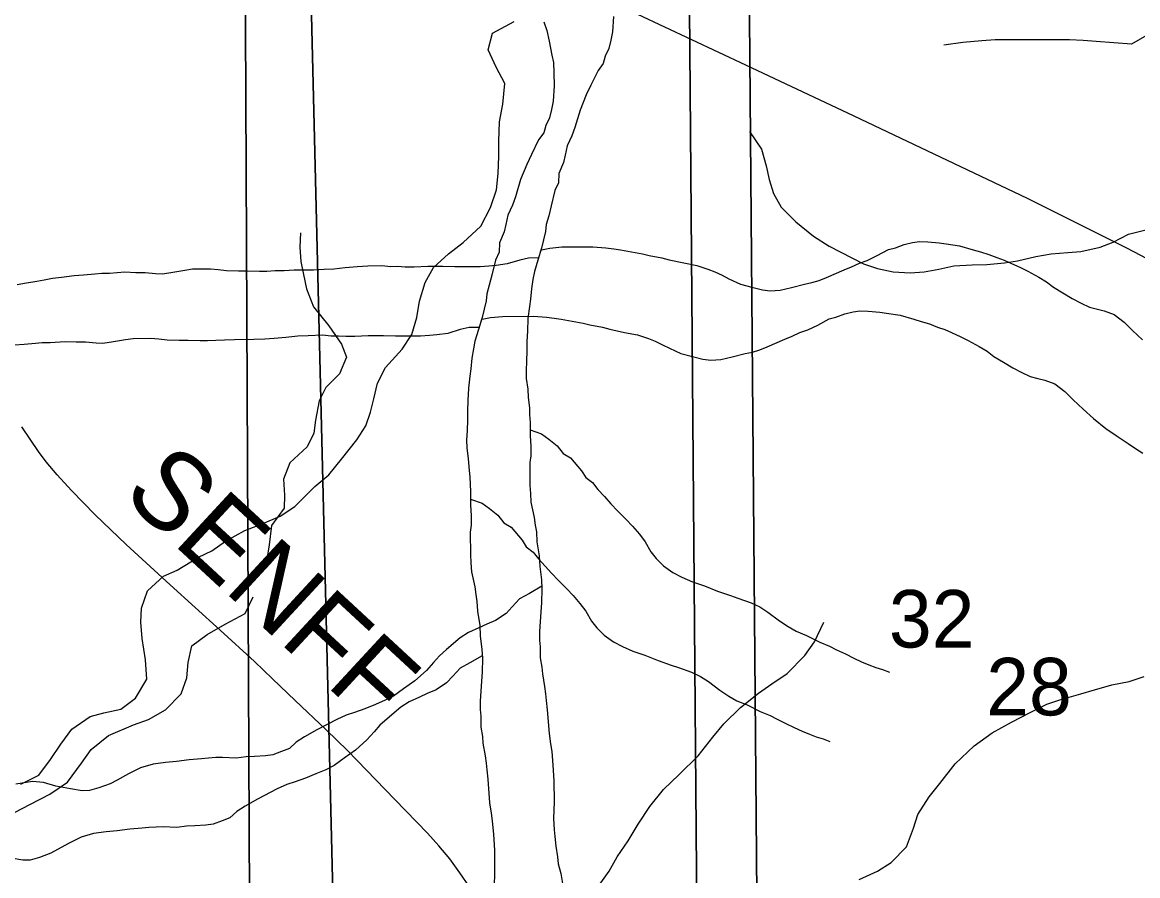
# Model space of a CAD drawing. Extents: x -21.1 to 50.3, y -4.9 to 22.1.
# Drawn here: x 6.307 to 7.119, y 17.303 to 17.924 of the extents above; entities that cross this region are included whole.
import ezdxf

# ---------------------------------------------------------------- set-up
doc = ezdxf.new("R2010")
doc.units = 0
for name, color, linetype in [('GM_X_Minor_River', 7, 'Continuous'), ('GM_X_Section', 7, 'Continuous'), ('GM_X_Section_Text', 7, 'Continuous'), ('GM_X_Township_Road', 7, 'Continuous'), ('GM_X_Township_Road_Text', 7, 'Continuous'), ('GM_X_US_Route', 7, 'Continuous')]:
    doc.layers.add(name, color=color, linetype=linetype)

msp = doc.modelspace()

# ---------------------------------------------------------------- linework, layer by layer
at = {"layer": 'GM_X_Minor_River'}
for points in [[(6.46887, 17.55403), (6.48147, 17.55877), (6.49447, 17.56428), (6.50522, 17.57133), (6.51988, 17.58592), (6.52989, 17.59451), (6.53918, 17.60576), (6.55041, 17.62003), (6.55703, 17.63018), (6.56022, 17.64001), (6.56265, 17.64985), (6.56549, 17.66121), (6.57136, 17.67251), (6.58334, 17.68601), (6.59034, 17.69654), (6.59395, 17.70902), (6.59604, 17.72076), (6.60005, 17.73438), (6.60629, 17.7453), (6.61708, 17.7554), (6.62784, 17.76359), (6.64057, 17.77555), (6.64761, 17.78912), (6.65199, 17.80197), (6.65331, 17.81373), (6.65388, 17.82626), (6.65368, 17.83728), (6.65427, 17.85132), (6.65675, 17.8642), (6.65813, 17.87938), (6.65186, 17.89125), (6.64597, 17.90387), (6.6492, 17.91598), (6.6649, 17.92448)], [(6.6865, 17.92424), (6.68882, 17.9178), (6.69038, 17.91021), (6.69235, 17.89996), (6.69352, 17.89465), (6.69394, 17.88706), (6.69399, 17.87756), (6.6933, 17.86654), (6.69219, 17.86045), (6.6907, 17.85437), (6.68806, 17.84865), (6.68657, 17.84333), (6.68279, 17.83837), (6.67752, 17.8277), (6.67414, 17.82047), (6.66963, 17.80943), (6.6659, 17.79687), (6.66365, 17.79078), (6.66026, 17.78354), (6.65878, 17.7767), (6.65767, 17.77137), (6.65428, 17.76338), (6.65394, 17.75654), (6.65131, 17.75082), (6.64871, 17.73979), (6.64685, 17.73257), (6.64498, 17.7261), (6.64463, 17.72116), (6.64165, 17.70899), (6.63903, 17.70023), (6.63641, 17.69186), (6.6353, 17.68616), (6.6342, 17.67931), (6.63348, 17.67171), (6.63275, 17.66639), (6.63166, 17.65765), (6.63133, 17.64853), (6.63099, 17.64093), (6.63102, 17.63447), (6.63069, 17.62649), (6.63035, 17.62003), (6.63038, 17.61395), (6.63156, 17.60636), (6.63198, 17.60029), (6.63278, 17.59269), (6.63281, 17.58775), (6.63322, 17.58206), (6.63327, 17.57256), (6.6337, 17.56459), (6.63374, 17.55775), (6.633, 17.55281), (6.6331, 17.53609), (6.63351, 17.5304), (6.63393, 17.52394), (6.63627, 17.51294), (6.63707, 17.50724), (6.63786, 17.50231), (6.63828, 17.49509), (6.63986, 17.48485), (6.64028, 17.47725), (6.64148, 17.46738), (6.64189, 17.46093), (6.64157, 17.45067), (6.64123, 17.44421), (6.64016, 17.42977), (6.6402, 17.42369), (6.64061, 17.41875), (6.64065, 17.41077)], [(6.73728, 17.92807), (6.73658, 17.91705), (6.73547, 17.91097), (6.73399, 17.90488), (6.73135, 17.89917), (6.72986, 17.89384), (6.72608, 17.88889), (6.72081, 17.87822), (6.71743, 17.87098), (6.71292, 17.85994), (6.70919, 17.84739), (6.70694, 17.8413), (6.70355, 17.83406), (6.70207, 17.82721), (6.70096, 17.82189), (6.69757, 17.81389), (6.69723, 17.80705), (6.6946, 17.80134), (6.692, 17.79031), (6.69013, 17.78308), (6.68827, 17.77661), (6.68791, 17.77167), (6.68493, 17.7595), (6.68232, 17.75075), (6.6797, 17.74238), (6.67859, 17.73667), (6.67749, 17.72983), (6.67677, 17.72223), (6.67604, 17.71691), (6.67495, 17.70816), (6.67461, 17.69904), (6.67428, 17.69145), (6.67431, 17.68499), (6.67398, 17.67701), (6.67363, 17.67055), (6.67367, 17.66447), (6.67485, 17.65688), (6.67527, 17.6508), (6.67607, 17.64321), (6.6761, 17.63827), (6.67651, 17.63257), (6.67656, 17.62308), (6.67699, 17.6151), (6.67703, 17.60827), (6.67629, 17.60332), (6.67639, 17.58661), (6.6768, 17.58091), (6.67722, 17.57446), (6.67956, 17.56345), (6.68036, 17.55776), (6.68115, 17.55283), (6.68157, 17.54561), (6.68315, 17.53536), (6.68357, 17.52777), (6.68476, 17.5179), (6.68518, 17.51144), (6.68486, 17.50118), (6.68451, 17.49472), (6.68345, 17.48028), (6.68349, 17.4742), (6.6839, 17.46927), (6.68394, 17.46129)], [(7.1272, 17.91528), (7.11469, 17.90807), (7.1018, 17.90883), (7.08891, 17.90996), (7.07944, 17.91072), (7.06958, 17.9111), (7.01538, 17.91109), (7.00552, 17.91033), (6.99187, 17.90919), (6.97785, 17.90729)], [(6.83642, 17.84432), (6.84514, 17.83143), (6.84854, 17.81929), (6.85081, 17.80943), (6.85384, 17.79919), (6.85952, 17.78933), (6.87013, 17.77871), (6.88301, 17.76809), (6.89438, 17.76089), (6.91939, 17.748), (6.92962, 17.74458), (6.94099, 17.74231), (6.9535, 17.74155), (6.96373, 17.74231), (6.97435, 17.74421), (6.98534, 17.74649), (6.99861, 17.74725), (7.00922, 17.74763), (7.02211, 17.74877), (7.03159, 17.75028), (7.04486, 17.75332), (7.05623, 17.75522), (7.06836, 17.75636), (7.07784, 17.75712), (7.09186, 17.76015), (7.10134, 17.76394), (7.11234, 17.76964), (7.12599, 17.77305)], [(6.50926, 17.7707), (6.50887, 17.76008), (6.50963, 17.74985), (6.51151, 17.74036), (6.51378, 17.72974), (6.51871, 17.71685), (6.53007, 17.70282), (6.53916, 17.68954), (6.54294, 17.68006), (6.53763, 17.66793), (6.52777, 17.65806), (6.52284, 17.6482), (6.52018, 17.63417), (6.51904, 17.62469), (6.5141, 17.61483), (6.50159, 17.60307), (6.49703, 17.59131), (6.49778, 17.57955), (6.4974, 17.57007), (6.48829, 17.55755), (6.48639, 17.54352), (6.48487, 17.5329)], [(6.68419, 17.75702), (6.68494, 17.75836), (6.69103, 17.75953), (6.69978, 17.76034), (6.72223, 17.76046), (6.73175, 17.75976), (6.73747, 17.75903), (6.74242, 17.7583), (6.75842, 17.75534), (6.76338, 17.75423), (6.77252, 17.75238), (6.77786, 17.75089), (6.78853, 17.74867), (6.79806, 17.74682), (6.80607, 17.74421), (6.81103, 17.74234), (6.81637, 17.73971), (6.82133, 17.73707), (6.82973, 17.73332), (6.83811, 17.73109), (6.84574, 17.72923), (6.85145, 17.7285), (6.85868, 17.72892), (6.86704, 17.73087), (6.87654, 17.7332), (6.88187, 17.73437), (6.88719, 17.73592), (6.89251, 17.73822), (6.90542, 17.74361), (6.91073, 17.74592), (6.91643, 17.74861), (6.92213, 17.75054), (6.92934, 17.754), (6.93769, 17.7586), (6.94263, 17.75977), (6.94909, 17.76209), (6.95517, 17.76364), (6.96011, 17.76443), (6.96621, 17.76408), (6.97458, 17.76337), (6.97954, 17.76263), (6.98944, 17.76117), (6.99935, 17.75818), (7.00469, 17.75669), (7.01079, 17.75483), (7.01651, 17.75258), (7.02185, 17.75071), (7.02682, 17.74846), (7.03368, 17.74545), (7.03903, 17.74282), (7.04705, 17.73831), (7.05277, 17.73492), (7.05774, 17.73115), (7.06462, 17.72701), (7.07149, 17.72287), (7.07798, 17.71948), (7.08409, 17.71648), (7.08981, 17.71499), (7.09476, 17.71388), (7.10201, 17.71126), (7.10927, 17.7056), (7.1154, 17.69956), (7.12267, 17.69276)], [(6.68279, 17.75231), (6.67546, 17.75223), (6.669, 17.75068), (6.65988, 17.74797), (6.65189, 17.74678), (6.64657, 17.74637), (6.6401, 17.74596), (6.62183, 17.74586), (6.61307, 17.74619), (6.60203, 17.74613), (6.59214, 17.7457), (6.58567, 17.74566), (6.58033, 17.74601), (6.57501, 17.74598), (6.56853, 17.74671), (6.55826, 17.74627), (6.55065, 17.74585), (6.5419, 17.74504), (6.53353, 17.74423), (6.52668, 17.74382), (6.51868, 17.74339), (6.5046, 17.74332), (6.49737, 17.7429), (6.4909, 17.74286), (6.48481, 17.74245), (6.47948, 17.74242), (6.47073, 17.74275), (6.46426, 17.74272), (6.4555, 17.74305), (6.44941, 17.74377), (6.4437, 17.74412), (6.43075, 17.74405), (6.42505, 17.74326), (6.4163, 17.74169), (6.4087, 17.74051), (6.40375, 17.74087), (6.39613, 17.74158), (6.38928, 17.74155), (6.38128, 17.74188), (6.37025, 17.74106), (6.36454, 17.74103), (6.35959, 17.74062), (6.35122, 17.73982), (6.34437, 17.7394), (6.33525, 17.73821), (6.32878, 17.73741), (6.32269, 17.73624), (6.31737, 17.73507), (6.30977, 17.73389), (6.30292, 17.73272)], [(6.6409, 17.7065), (6.64165, 17.70784), (6.64774, 17.70902), (6.65649, 17.70983), (6.67894, 17.70995), (6.68846, 17.70924), (6.69418, 17.70851), (6.69913, 17.70778), (6.71513, 17.70483), (6.72009, 17.70372), (6.72923, 17.70187), (6.73457, 17.70038), (6.74524, 17.69815), (6.75477, 17.69631), (6.76278, 17.69369), (6.76774, 17.69182), (6.77308, 17.68919), (6.77804, 17.68656), (6.78644, 17.68281), (6.79482, 17.68057), (6.80245, 17.67872), (6.80816, 17.67799), (6.81539, 17.6784), (6.82375, 17.68035), (6.83326, 17.68268), (6.83858, 17.68385), (6.8439, 17.6854), (6.84922, 17.68771), (6.86213, 17.6931), (6.86745, 17.6954), (6.87314, 17.6981), (6.87884, 17.70003), (6.88605, 17.70348), (6.8944, 17.70809), (6.89934, 17.70925), (6.9058, 17.71157), (6.91188, 17.71312), (6.91682, 17.71391), (6.92292, 17.71356), (6.9313, 17.71285), (6.93625, 17.71212), (6.94615, 17.71065), (6.95606, 17.70767), (6.9614, 17.70618), (6.9675, 17.70431), (6.97323, 17.70206), (6.97856, 17.70019), (6.98353, 17.69794), (6.99039, 17.69494), (6.99574, 17.69231), (7.00376, 17.68779), (7.00949, 17.68441), (7.01445, 17.68064), (7.02133, 17.67649), (7.0282, 17.67235), (7.03469, 17.66897), (7.0408, 17.66596), (7.04652, 17.66448), (7.05147, 17.66336), (7.05872, 17.66074), (7.06598, 17.65509), (7.07211, 17.64904), (7.07938, 17.64224), (7.08703, 17.63545), (7.09582, 17.62828), (7.10347, 17.623), (7.11225, 17.61735), (7.1176, 17.61358), (7.12295, 17.61019)], [(6.6395, 17.70179), (6.63217, 17.70172), (6.62571, 17.70016), (6.61659, 17.69745), (6.6086, 17.69627), (6.60328, 17.69586), (6.59681, 17.69544), (6.57854, 17.69534), (6.56978, 17.69568), (6.55874, 17.69561), (6.54885, 17.69518), (6.54238, 17.69515), (6.53705, 17.6955), (6.53172, 17.69547), (6.52524, 17.69619), (6.51497, 17.69575), (6.50736, 17.69533), (6.49861, 17.69453), (6.49024, 17.69372), (6.48339, 17.6933), (6.4754, 17.69288), (6.46131, 17.6928), (6.45408, 17.69238), (6.44761, 17.69235), (6.44152, 17.69193), (6.4362, 17.6919), (6.42744, 17.69224), (6.42097, 17.6922), (6.41221, 17.69253), (6.40612, 17.69326), (6.40041, 17.69361), (6.38746, 17.69354), (6.38176, 17.69275), (6.37301, 17.69118), (6.36541, 17.69), (6.36046, 17.69035), (6.35284, 17.69107), (6.34599, 17.69103), (6.33799, 17.69137), (6.32696, 17.69055), (6.32125, 17.69051), (6.31631, 17.69011), (6.30793, 17.6893), (6.30108, 17.68889)], [(6.67654, 17.62726), (6.68493, 17.62426), (6.69028, 17.62049), (6.6964, 17.61559), (6.70062, 17.60991), (6.70596, 17.6069), (6.71401, 17.59745), (6.71708, 17.59253), (6.72205, 17.58876), (6.72589, 17.58384), (6.73086, 17.57855), (6.73546, 17.57326), (6.74044, 17.56796), (6.74656, 17.56192), (6.75116, 17.55701), (6.75614, 17.55134), (6.76036, 17.54566), (6.76459, 17.53847), (6.76842, 17.53355), (6.77378, 17.52826), (6.78066, 17.52336), (6.78715, 17.51998), (6.79478, 17.5166), (6.80355, 17.51361), (6.81309, 17.50986), (6.82262, 17.50649), (6.82796, 17.50462), (6.8375, 17.50126), (6.84398, 17.49825), (6.84971, 17.49448), (6.85812, 17.48807), (6.86462, 17.48393), (6.87035, 17.48054), (6.87798, 17.47754), (6.88752, 17.47266), (6.89477, 17.46966), (6.89973, 17.46703), (6.90622, 17.46402), (6.91233, 17.46102), (6.91805, 17.45839), (6.92339, 17.45614), (6.92835, 17.45427), (6.93331, 17.45277), (6.93827, 17.4509)], [(6.63325, 17.57674), (6.64164, 17.57375), (6.64699, 17.56998), (6.65311, 17.56507), (6.65733, 17.5594), (6.66267, 17.55639), (6.67072, 17.54693), (6.6738, 17.54201), (6.67876, 17.53824), (6.6826, 17.53332), (6.68758, 17.52803), (6.69217, 17.52274), (6.69715, 17.51745), (6.70327, 17.5114), (6.70787, 17.50649), (6.71285, 17.50082), (6.71707, 17.49515), (6.7213, 17.48795), (6.72513, 17.48303), (6.73049, 17.47774), (6.73737, 17.47284), (6.74386, 17.46946), (6.75149, 17.46608), (6.76026, 17.46309), (6.7698, 17.45934), (6.77933, 17.45598), (6.78467, 17.45411), (6.79421, 17.45074), (6.80069, 17.44774), (6.80642, 17.44397), (6.81484, 17.43756), (6.82133, 17.43341), (6.82706, 17.43003), (6.83469, 17.42703), (6.84423, 17.42214), (6.85148, 17.41914), (6.85644, 17.41651), (6.86293, 17.41351), (6.86904, 17.4105), (6.87476, 17.40787), (6.8801, 17.40562), (6.88506, 17.40375), (6.89002, 17.40226), (6.89498, 17.40039)], [(6.30571, 17.36922), (6.31873, 17.37586), (6.32726, 17.38713), (6.33465, 17.39841), (6.3428, 17.40931), (6.35624, 17.4186), (6.36615, 17.42111), (6.37835, 17.42396), (6.38911, 17.43178), (6.3973, 17.44571), (6.39638, 17.45978), (6.39396, 17.47539), (6.393, 17.48718), (6.39354, 17.49743), (6.39791, 17.5099), (6.40948, 17.52074), (6.41942, 17.52515), (6.43514, 17.5344), (6.44471, 17.5392), (6.45469, 17.54626), (6.46887, 17.55403)], [(6.68506, 17.51329), (6.67607, 17.50797), (6.66886, 17.50413), (6.66356, 17.49841), (6.65902, 17.49344), (6.65143, 17.48846), (6.64498, 17.48577), (6.63928, 17.48308), (6.63169, 17.47962), (6.62562, 17.47579), (6.61577, 17.46737), (6.61047, 17.46279), (6.60631, 17.45783), (6.60101, 17.4521), (6.59268, 17.44446), (6.58434, 17.43871), (6.57714, 17.43335), (6.57106, 17.43028), (6.56385, 17.4272), (6.55625, 17.42412), (6.54865, 17.42142), (6.54258, 17.41949), (6.53574, 17.41641), (6.52132, 17.40874), (6.51221, 17.40375), (6.50615, 17.39992), (6.50122, 17.39533), (6.49552, 17.39302), (6.48907, 17.39071), (6.48374, 17.38992), (6.47575, 17.38949), (6.46966, 17.38908), (6.46243, 17.38828), (6.45254, 17.38861), (6.44759, 17.38858), (6.44226, 17.38817), (6.43732, 17.38776), (6.42818, 17.38695), (6.41906, 17.38576), (6.41107, 17.38496), (6.40194, 17.38377), (6.39282, 17.38106), (6.38409, 17.37684), (6.37574, 17.37223), (6.37081, 17.36955), (6.36245, 17.36646), (6.35561, 17.36452), (6.35028, 17.36449), (6.3419, 17.36597), (6.33657, 17.3667), (6.33123, 17.36781), (6.32208, 17.37042), (6.31408, 17.37113), (6.30191, 17.36917)], [(6.30149, 17.3489), (6.31216, 17.35452), (6.32663, 17.36202), (6.33958, 17.37067), (6.34992, 17.38464), (6.35682, 17.39447), (6.36941, 17.40463), (6.38768, 17.41249), (6.39871, 17.41621), (6.4109, 17.42335), (6.42236, 17.43504), (6.42661, 17.44677), (6.42744, 17.45777), (6.43018, 17.46989), (6.44123, 17.47817), (6.45457, 17.48568), (6.46904, 17.49356), (6.47481, 17.50566)], [(6.85273, 17.44226), (6.86378, 17.44978), (6.87677, 17.46297), (6.88367, 17.47279), (6.89059, 17.48717)], [(6.64177, 17.46277), (6.63278, 17.45746), (6.62557, 17.45362), (6.62027, 17.44789), (6.61573, 17.44293), (6.60815, 17.43795), (6.60169, 17.43525), (6.59599, 17.43256), (6.5884, 17.4291), (6.58233, 17.42527), (6.57248, 17.41686), (6.56718, 17.41227), (6.56302, 17.40731), (6.55772, 17.40158), (6.54939, 17.39394), (6.54105, 17.3882), (6.53385, 17.38284), (6.52777, 17.37977), (6.52056, 17.37669), (6.51296, 17.37361), (6.50537, 17.3709), (6.49929, 17.36897), (6.49245, 17.3659), (6.47803, 17.35822), (6.46892, 17.35323), (6.46286, 17.3494), (6.45793, 17.34482), (6.45224, 17.3425), (6.44578, 17.34019), (6.44045, 17.3394), (6.43246, 17.33898), (6.42637, 17.33857), (6.41915, 17.33776), (6.40925, 17.33809), (6.4043, 17.33806), (6.39897, 17.33765), (6.39403, 17.33725), (6.3849, 17.33644), (6.37577, 17.33525), (6.36778, 17.33444), (6.35865, 17.33326), (6.34953, 17.33055), (6.3408, 17.32632), (6.33245, 17.32172), (6.32752, 17.31903), (6.31916, 17.31594), (6.31232, 17.31401), (6.30699, 17.31398), (6.29861, 17.31545)], [(6.68394, 17.46129), (6.68512, 17.45446), (6.68553, 17.44952), (6.6871, 17.44041), (6.68789, 17.4351), (6.6883, 17.43016), (6.6891, 17.42333), (6.69034, 17.40624), (6.69152, 17.39865), (6.69232, 17.39296), (6.69313, 17.38308), (6.69396, 17.37169), (6.69404, 17.3565), (6.69373, 17.34434), (6.69416, 17.33598), (6.69457, 17.33105), (6.69537, 17.32421), (6.69655, 17.31624), (6.69696, 17.31131), (6.6989, 17.3041), (6.70009, 17.29689)], [(6.91615, 17.29993), (6.92954, 17.3058), (6.93951, 17.31211), (6.95071, 17.32372), (6.95586, 17.33731), (6.95905, 17.34714), (6.96722, 17.35993), (6.97497, 17.36969), (6.98621, 17.38396), (7.00009, 17.39704), (7.01315, 17.40672), (7.02732, 17.41448), (7.04072, 17.4215), (7.05297, 17.42739), (7.06252, 17.43066), (7.07778, 17.43499), (7.0877, 17.43788), (7.10029, 17.44149), (7.11286, 17.44396), (7.12393, 17.44759)], [(6.72692, 17.29582), (6.73419, 17.30602), (6.73995, 17.31623), (6.748, 17.32794), (6.75529, 17.34004), (6.76372, 17.35288), (6.77367, 17.36534), (6.78513, 17.37627), (6.79888, 17.38985), (6.80959, 17.40344), (6.81762, 17.41326), (6.82985, 17.42494), (6.84282, 17.43549), (6.85273, 17.44226)], [(6.64065, 17.41077), (6.64183, 17.40394), (6.64224, 17.39901), (6.64381, 17.3899), (6.6446, 17.38458), (6.64501, 17.37965), (6.64581, 17.37281), (6.64705, 17.35572), (6.64823, 17.34814), (6.64903, 17.34244), (6.64985, 17.33257), (6.65067, 17.32118), (6.65075, 17.30598), (6.65044, 17.29382)]]:
    msp.add_lwpolyline(points, dxfattribs=at)
at = {"layer": 'GM_X_Section'}
for points in [[(5.45742, 18.14589), (6.46827, 18.13471), (6.47301, 17.12604), (6.41542, 17.12601), (5.45266, 17.13084)], [(6.46827, 18.13471), (7.46215, 18.13462), (7.47526, 17.13233), (7.40705, 17.13199), (6.47301, 17.12604)], [(5.81893, 17.99203), (6.83569, 18.01448), (6.84408, 16.99761), (5.83147, 16.97938)], [(6.83569, 18.01448), (7.84977, 17.99671), (7.85852, 16.9825), (7.38497, 16.99642), (6.84408, 16.99761)], [(5.48815, 17.97251), (6.51666, 17.95921), (6.54146, 16.94121), (5.52017, 16.94387)], [(5.77564, 17.94152), (6.7924, 17.96396), (6.8008, 16.94709), (5.78818, 16.92886)], [(7.54061, 17.96333), (7.56617, 16.93816), (6.54146, 16.94121), (6.51666, 17.95921)], [(6.7924, 17.96396), (7.80649, 17.9462), (7.81523, 16.93198), (7.34169, 16.9459), (6.8008, 16.94709)]]:
    msp.add_lwpolyline(points, close=True, dxfattribs=at)
at = {"layer": 'GM_X_Township_Road'}
msp.add_lwpolyline([(6.63232, 17.29444), (6.62543, 17.3048), (6.61805, 17.3148), (6.61017, 17.32442), (6.60183, 17.33364), (6.57804, 17.35813), (6.54345, 17.39371), (6.52793, 17.40886), (6.50544, 17.4301), (6.48898, 17.44591), (6.4759, 17.45847), (6.4508, 17.48146), (6.4143, 17.51442), (6.38232, 17.54384), (6.35987, 17.56527), (6.34251, 17.583), (6.33202, 17.59439), (6.3241, 17.60388), (6.31857, 17.61131), (6.30643, 17.6293)], dxfattribs=at)
at = {"layer": 'GM_X_US_Route'}
msp.add_lwpolyline([(6.42119, 18.08703), (6.52705, 18.03708), (6.5974, 18.00391), (6.65083, 17.97888), (6.69589, 17.9576), (6.83344, 17.89297), (6.91234, 17.85587), (7.03858, 17.79596), (7.11094, 17.75966), (7.16049, 17.73364)], dxfattribs=at)

# ---------------------------------------------------------------- texts
at = {"layer": 'GM_X_Section_Text'}
for s, p in [('32', (6.93794, 17.46873)), ('28', (7.00886, 17.41932))]:
    msp.add_text(s, height=0.041856, rotation=0.00001, dxfattribs=at).set_placement(p)
at = {"layer": 'GM_X_Township_Road_Text'}
msp.add_text('SENFF', height=0.056818, rotation=317.22705, dxfattribs=at).set_placement((6.37829, 17.57923))

doc.saveas('drawing.dxf')
